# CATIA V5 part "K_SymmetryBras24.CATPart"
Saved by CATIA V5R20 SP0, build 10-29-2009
Part number: Symmetry of Bras24
Bounding box of the stored display mesh (mm): x -12 to 2, y -5 to 143.568, z -84.984 to 4.998
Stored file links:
  G:\Khaled_CFAO_2011\SIL\SIL_GR2\zthiebault\Khaled\CAD_ThinkMOTION\K_SymmetryBras24.CATPart
  G:\Khaled_CFAO_2011\SIL\SIL_GR2\zthiebault\Khaled\CAD_ThinkMOTION\K_Bras24.CATPart
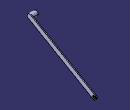
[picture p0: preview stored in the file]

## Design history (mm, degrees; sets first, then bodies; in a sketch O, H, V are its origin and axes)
Body1 (main body)
  Body2 "Corps du corps principal d'origine"
    Solid1: linked copy from another document
  Assemble1: tool Body2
